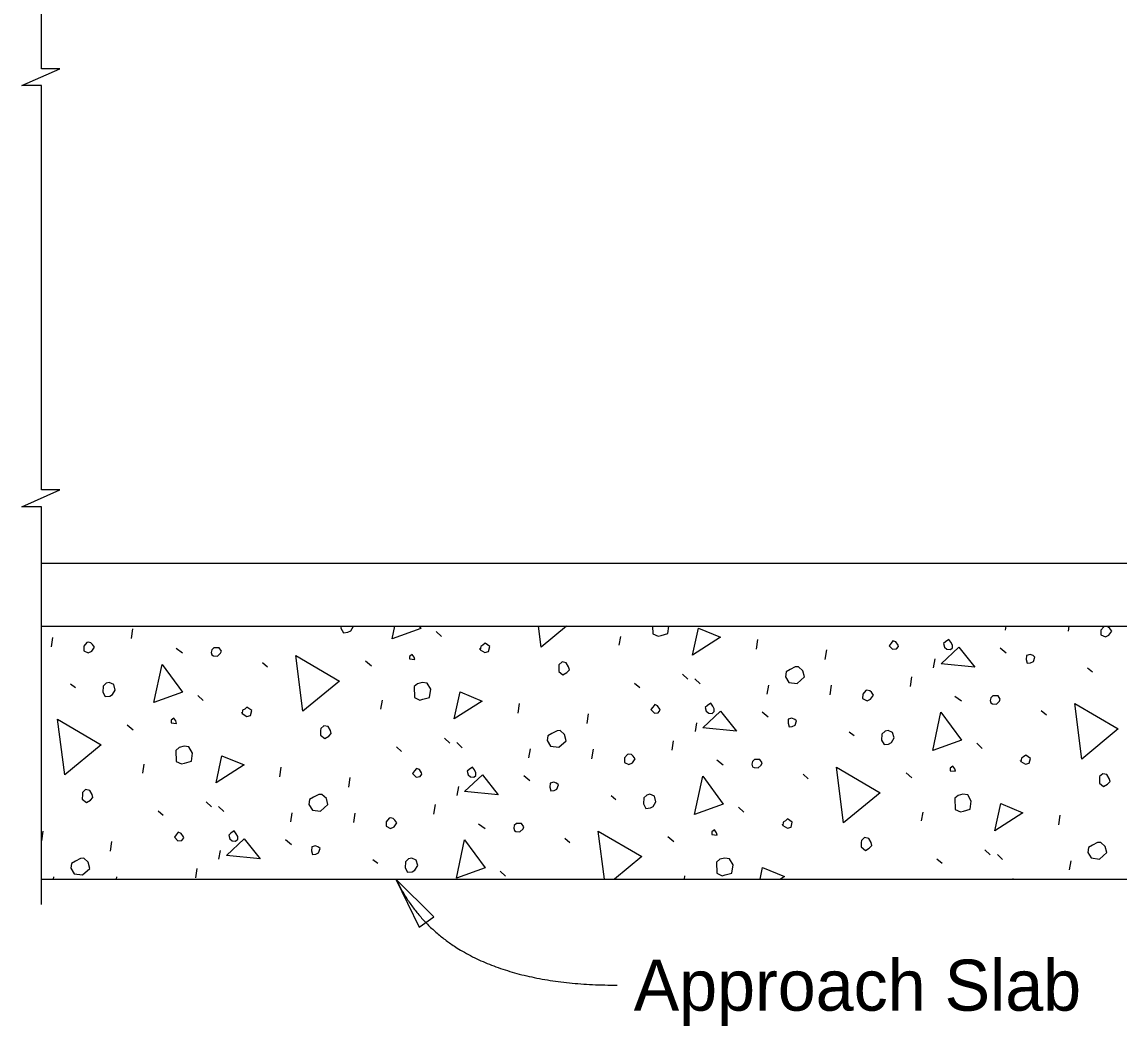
# Model space of a CAD drawing. Extents: x 120680.2 to 120752.3, y 120667.6 to 120707.3.
# Drawn here: x 120705.176 to 120709.513, y 120695.548 to 120699.517 of the extents above; entities that cross this region are included whole.
import ezdxf

# ---------------------------------------------------------------- set-up
doc = ezdxf.new("R2010")
doc.units = 0
for name, color, linetype in [('Dimension', 7, 'Continuous'), ('ParapetConc', 7, 'Continuous'), ('Patterning', 7, 'Continuous'), ('TextStructures', 7, 'Continuous')]:
    doc.layers.add(name, color=color, linetype=linetype)

msp = doc.modelspace()

# ---------------------------------------------------------------- linework, layer by layer
at = {"layer": 'Dimension'}
for points in [[(120705.2532, 120698.3779), (120705.2532, 120699.2651), (120705.1757, 120699.2651), (120705.3257, 120699.3314), (120705.2532, 120699.3314), (120705.2532, 120699.907)], [(120705.2532, 120696.0279), (120705.2532, 120697.6005), (120705.1757, 120697.6005), (120705.3257, 120697.6668), (120705.2532, 120697.6668), (120705.2532, 120698.3779)]]:
    msp.add_lwpolyline(points, dxfattribs=at)
msp.add_lwpolyline([(120706.6543, 120696.1279), (120706.7465, 120695.9379), (120706.8039, 120695.9788)], close=True, dxfattribs=at)
msp.add_open_spline([(120706.6543, 120696.1279), (120706.8547, 120695.7093), (120707.5288, 120695.7093)], degree=2, dxfattribs=at)
at = {"layer": 'ParapetConc'}
for p, q in [((120705.2532, 120697.3779), (120712.7028, 120697.3779)), ((120705.2532, 120697.1279), (120715.7028, 120697.1279)), ((120705.2532, 120696.1279), (120715.7028, 120696.1279))]:
    msp.add_line(p, q, dxfattribs=at)
at = {"layer": 'Patterning'}
for p, q in [((120705.6091, 120697.0796), (120705.6145, 120697.1173)), ((120706.6394, 120697.0787), (120706.6499, 120697.1279)), ((120706.813, 120697.1071), (120706.8339, 120697.0869)), ((120707.2282, 120697.045), (120707.2177, 120697.1279)), ((120707.3288, 120697.1279), (120707.2282, 120697.045)), ((120709.0633, 120697.1122), (120709.066, 120697.1279)), ((120709.3126, 120697.1092), (120709.3153, 120697.1279)), ((120705.2919, 120697.0464), (120705.2973, 120697.0841)), ((120707.5368, 120697.0526), (120707.5428, 120697.0879)), ((120708.0792, 120697.0375), (120708.0846, 120697.0752)), ((120705.785, 120697.0413), (120705.8108, 120697.0223)), ((120708.3515, 120696.9966), (120708.357, 120697.0343)), ((120709.0433, 120697.0422), (120709.0667, 120697.0225)), ((120706.1261, 120696.9852), (120706.1465, 120696.9674)), ((120706.5336, 120696.9908), (120706.5569, 120696.9712)), ((120708.7796, 120696.9637), (120708.7857, 120696.999)), ((120707.7873, 120696.9386), (120707.8083, 120696.9183)), ((120709.3878, 120696.9637), (120709.4075, 120696.9482)), ((120705.3671, 120696.9009), (120705.3868, 120696.8854)), ((120707.5975, 120696.9032), (120707.6178, 120696.8854)), ((120707.8361, 120696.9206), (120707.8571, 120696.9003)), ((120708.1216, 120696.8599), (120708.1276, 120696.8952)), ((120708.3709, 120696.8568), (120708.3763, 120696.8945)), ((120708.6881, 120696.89), (120708.6935, 120696.9277)), ((120705.8712, 120696.8548), (120705.8922, 120696.8345)), ((120708.864, 120696.8518), (120708.8898, 120696.8328)), ((120706.595, 120696.8002), (120706.6011, 120696.8355)), ((120707.1374, 120696.7851), (120707.1428, 120696.8228)), ((120707.4097, 120696.7442), (120707.4152, 120696.7819)), ((120708.1015, 120696.7898), (120708.1249, 120696.7702)), ((120709.2051, 120696.7956), (120709.2254, 120696.7778)), ((120705.5918, 120696.7385), (120705.6152, 120696.7189)), ((120707.8378, 120696.7114), (120707.8439, 120696.7467)), ((120706.8455, 120696.6862), (120706.8665, 120696.6659)), ((120707.7463, 120696.6377), (120707.7517, 120696.6754)), ((120708.4461, 120696.7113), (120708.4657, 120696.6959)), ((120706.6557, 120696.6509), (120706.676, 120696.633)), ((120706.8944, 120696.6682), (120706.9153, 120696.648)), ((120707.1798, 120696.6075), (120707.1859, 120696.6428)), ((120707.4291, 120696.6045), (120707.4345, 120696.6421)), ((120708.9502, 120696.6652), (120708.9711, 120696.645)), ((120707.9222, 120696.5994), (120707.948, 120696.5804)), ((120705.6532, 120696.5479), (120705.6593, 120696.5832)), ((120706.1956, 120696.5328), (120706.201, 120696.5705)), ((120708.2633, 120696.5433), (120708.2836, 120696.5254)), ((120708.6708, 120696.5489), (120708.6941, 120696.5293)), ((120706.468, 120696.4919), (120706.4734, 120696.5296)), ((120707.1597, 120696.5375), (120707.1831, 120696.5178)), ((120706.8961, 120696.459), (120706.9021, 120696.4943)), ((120707.5043, 120696.459), (120707.524, 120696.4435)), ((120705.9038, 120696.4339), (120705.9247, 120696.4136)), ((120705.9526, 120696.4159), (120705.9735, 120696.3956)), ((120706.8045, 120696.3853), (120706.8099, 120696.423)), ((120708.0084, 120696.4129), (120708.0294, 120696.3926)), ((120705.7139, 120696.3985), (120705.7343, 120696.3807)), ((120706.238, 120696.3552), (120706.2441, 120696.3905)), ((120706.4873, 120696.3521), (120706.4927, 120696.3898)), ((120708.7322, 120696.3583), (120708.7383, 120696.3936)), ((120709.2746, 120696.3432), (120709.28, 120696.3809)), ((120706.9804, 120696.3471), (120707.0062, 120696.3281)), ((120705.2538, 120696.2804), (120705.2593, 120696.3181)), ((120706.218, 120696.2851), (120706.2413, 120696.2655)), ((120707.3216, 120696.2909), (120707.3419, 120696.2731)), ((120707.729, 120696.2966), (120707.7524, 120696.277)), ((120705.5262, 120696.2395), (120705.5316, 120696.2772)), ((120705.9543, 120696.2067), (120705.9604, 120696.242)), ((120708.9827, 120696.2443), (120709.0037, 120696.224)), ((120706.5625, 120696.2066), (120706.5822, 120696.1912)), ((120708.7929, 120696.209), (120708.8132, 120696.1911)), ((120709.0315, 120696.2263), (120709.0525, 120696.2061)), ((120709.317, 120696.1656), (120709.3231, 120696.2009)), ((120705.8627, 120696.133), (120705.8682, 120696.1707)), ((120707.0666, 120696.1605), (120707.0876, 120696.1403)), ((120705.3006, 120696.1279), (120705.3023, 120696.1381)), ((120705.5496, 120696.1279), (120705.551, 120696.1375)), ((120707.7942, 120696.1279), (120707.7965, 120696.1413)), ((120708.3381, 120696.1279), (120708.3382, 120696.1285))]:
    msp.add_line(p, q, dxfattribs=at)
for points in [[(120706.4372, 120697.1279), (120706.4368, 120697.1202), (120706.4468, 120697.1022), (120706.4643, 120697.1043), (120706.4758, 120697.1099), (120706.4861, 120697.1279)], [(120706.7465, 120697.1279), (120706.7527, 120697.1195), (120706.6394, 120697.0787)], [(120707.6685, 120697.1279), (120707.6694, 120697.0985), (120707.6902, 120697.0885), (120707.7023, 120697.0918), (120707.7288, 120697.0989), (120707.7327, 120697.1279)], [(120707.8267, 120697.0138), (120707.8497, 120697.1209), (120707.9371, 120697.0848), (120707.8267, 120697.0138)], [(120709.4411, 120697.1125), (120709.4408, 120697.0943), (120709.4586, 120697.0861), (120709.4724, 120697.0924), (120709.4837, 120697.1084), (120709.4756, 120697.1192), (120709.4688, 120697.1251), (120709.4579, 120697.1274), (120709.453, 120697.1261), (120709.4411, 120697.1125)], [(120705.4204, 120697.0497), (120705.4201, 120697.0315), (120705.4378, 120697.0234), (120705.4517, 120697.0296), (120705.4629, 120697.0456), (120705.4548, 120697.0564), (120705.4481, 120697.0623), (120705.4371, 120697.0646), (120705.4323, 120697.0633), (120705.4204, 120697.0497)], [(120708.6035, 120697.0511), (120708.6177, 120697.0368), (120708.6328, 120697.0383), (120708.6405, 120697.0481), (120708.6392, 120697.0529), (120708.6305, 120697.0661), (120708.6189, 120697.0708), (120708.6112, 120697.061), (120708.6035, 120697.0511)], [(120708.8225, 120697.0451), (120708.8323, 120697.0374), (120708.8457, 120697.0358), (120708.8541, 120697.0432), (120708.8539, 120697.0535), (120708.8482, 120697.065), (120708.8402, 120697.0757), (120708.827, 120697.067), (120708.8186, 120697.0596), (120708.8225, 120697.0451)], [(120705.9267, 120697.0146), (120705.9329, 120697.0111), (120705.9486, 120697.0101), (120705.9612, 120697.0212), (120705.9641, 120697.0298), (120705.9554, 120697.043), (120705.9348, 120697.0426), (120705.9264, 120697.0352), (120705.9242, 120697.0243), (120705.9267, 120697.0146)], [(120706.9876, 120697.0349), (120707.006, 120697.0243), (120707.0205, 120697.0281), (120707.0256, 120697.0476), (120707.0066, 120697.0607), (120706.9982, 120697.0532), (120706.9892, 120697.0482), (120706.9876, 120697.0349), (120706.9863, 120697.0397)], [(120708.8091, 120696.9794), (120708.8795, 120697.0449), (120708.9421, 120696.9659), (120708.8091, 120696.9794)], [(120705.6976, 120696.8264), (120705.7297, 120696.9773), (120705.811, 120696.8671), (120705.6976, 120696.8264)], [(120706.2864, 120696.7926), (120706.2585, 120697.0129), (120706.4306, 120696.9115), (120706.2864, 120696.7926)], [(120706.7075, 120696.9986), (120706.7287, 120696.9966), (120706.7261, 120697.0062), (120706.7181, 120697.017), (120706.7073, 120697.0089), (120706.7075, 120696.9986)], [(120707.298, 120696.9679), (120707.2977, 120696.9497), (120707.3143, 120696.9361), (120707.33, 120696.9454), (120707.3401, 120696.9559), (120707.3369, 120696.968), (120707.3275, 120696.9836), (120707.3111, 120696.9869), (120707.2985, 120696.9758), (120707.298, 120696.9679)], [(120709.1459, 120696.9972), (120709.1498, 120696.9827), (120709.1625, 120696.9835), (120709.174, 120696.9892), (120709.1797, 120697.0063), (120709.173, 120697.0122), (120709.1614, 120697.0169), (120709.1469, 120697.013), (120709.1459, 120696.9972)], [(120708.1938, 120696.9284), (120708.2075, 120696.9062), (120708.2397, 120696.9019), (120708.269, 120696.9279), (120708.2625, 120696.952), (120708.2453, 120696.9681), (120708.2326, 120696.9673), (120708.2121, 120696.9566), (120708.1965, 120696.9473), (120708.1938, 120696.9284)], [(120705.4964, 120696.8915), (120705.495, 120696.8679), (120705.505, 120696.8498), (120705.5226, 120696.8519), (120705.534, 120696.8576), (120705.5446, 120696.876), (120705.5388, 120696.8977), (120705.5211, 120696.9059), (120705.509, 120696.9027), (120705.4964, 120696.8915)], [(120706.7263, 120696.8898), (120706.7276, 120696.8461), (120706.7484, 120696.8362), (120706.7605, 120696.8394), (120706.787, 120696.8465), (120706.7914, 120696.8787), (120706.777, 120696.9034), (120706.7582, 120696.9061), (120706.7388, 120696.9009), (120706.7263, 120696.8898)], [(120706.8849, 120696.7615), (120706.908, 120696.8686), (120706.9953, 120696.8325), (120706.8849, 120696.7615)], [(120708.4994, 120696.8602), (120708.4991, 120696.842), (120708.5168, 120696.8338), (120708.5306, 120696.8401), (120708.5419, 120696.856), (120708.5338, 120696.8668), (120708.527, 120696.8728), (120708.5161, 120696.875), (120708.5113, 120696.8737), (120708.4994, 120696.8602)], [(120709.0057, 120696.825), (120709.0118, 120696.8215), (120709.0276, 120696.8206), (120709.0402, 120696.8317), (120709.0431, 120696.8402), (120709.0343, 120696.8534), (120709.0137, 120696.8531), (120709.0054, 120696.8456), (120709.0031, 120696.8347), (120709.0057, 120696.825)], [(120706.0459, 120696.7825), (120706.0642, 120696.7719), (120706.0787, 120696.7758), (120706.0839, 120696.7953), (120706.0648, 120696.8083), (120706.0565, 120696.8009), (120706.0475, 120696.7959), (120706.0459, 120696.7825), (120706.0446, 120696.7874)], [(120707.6617, 120696.7988), (120707.6759, 120696.7845), (120707.691, 120696.7859), (120707.6988, 120696.7958), (120707.6975, 120696.8006), (120707.6887, 120696.8138), (120707.6771, 120696.8185), (120707.6694, 120696.8086), (120707.6617, 120696.7988)], [(120707.8807, 120696.7928), (120707.8906, 120696.7851), (120707.9039, 120696.7835), (120707.9123, 120696.7909), (120707.9121, 120696.8012), (120707.9065, 120696.8126), (120707.8984, 120696.8234), (120707.8852, 120696.8147), (120707.8768, 120696.8073), (120707.8807, 120696.7928)], [(120709.3654, 120696.6031), (120709.3375, 120696.8233), (120709.5096, 120696.7219), (120709.3654, 120696.6031)], [(120705.3447, 120696.5403), (120705.3167, 120696.7606), (120705.4888, 120696.6591), (120705.3447, 120696.5403)], [(120705.7657, 120696.7463), (120705.787, 120696.7442), (120705.7844, 120696.7539), (120705.7763, 120696.7646), (120705.7655, 120696.7566), (120705.7657, 120696.7463)], [(120707.8673, 120696.727), (120707.9377, 120696.7925), (120708.0003, 120696.7135), (120707.8673, 120696.727)], [(120708.2042, 120696.7448), (120708.208, 120696.7304), (120708.2208, 120696.7312), (120708.2322, 120696.7368), (120708.238, 120696.7539), (120708.2312, 120696.7599), (120708.2196, 120696.7645), (120708.2051, 120696.7606), (120708.2042, 120696.7448)], [(120708.7766, 120696.6368), (120708.8086, 120696.7878), (120708.8899, 120696.6775), (120708.7766, 120696.6368)], [(120706.3563, 120696.7156), (120706.356, 120696.6974), (120706.3726, 120696.6837), (120706.3882, 120696.6931), (120706.3983, 120696.7036), (120706.3951, 120696.7156), (120706.3857, 120696.7312), (120706.3693, 120696.7346), (120706.3567, 120696.7235), (120706.3563, 120696.7156)], [(120707.252, 120696.6761), (120707.2657, 120696.6539), (120707.2979, 120696.6496), (120707.3272, 120696.6755), (120707.3207, 120696.6997), (120707.3035, 120696.7157), (120707.2908, 120696.7149), (120707.2703, 120696.7043), (120707.2547, 120696.6949), (120707.252, 120696.6761)], [(120708.5754, 120696.702), (120708.574, 120696.6783), (120708.584, 120696.6603), (120708.6015, 120696.6624), (120708.613, 120696.668), (120708.6236, 120696.6864), (120708.6177, 120696.7081), (120708.6, 120696.7163), (120708.5879, 120696.7131), (120708.5754, 120696.702)], [(120705.7845, 120696.6374), (120705.7859, 120696.5938), (120705.8066, 120696.5838), (120705.8187, 120696.5871), (120705.8453, 120696.5942), (120705.8496, 120696.6264), (120705.8352, 120696.651), (120705.8164, 120696.6537), (120705.7971, 120696.6486), (120705.7845, 120696.6374)], [(120705.9431, 120696.5091), (120705.9662, 120696.6162), (120706.0535, 120696.5801), (120705.9431, 120696.5091)], [(120707.5576, 120696.6078), (120707.5573, 120696.5896), (120707.575, 120696.5814), (120707.5889, 120696.5877), (120707.6001, 120696.6037), (120707.592, 120696.6145), (120707.5853, 120696.6204), (120707.5743, 120696.6227), (120707.5695, 120696.6214), (120707.5576, 120696.6078)], [(120708.0639, 120696.5727), (120708.0701, 120696.5692), (120708.0858, 120696.5682), (120708.0984, 120696.5793), (120708.1013, 120696.5879), (120708.0926, 120696.6011), (120708.072, 120696.6007), (120708.0636, 120696.5933), (120708.0613, 120696.5823), (120708.0639, 120696.5727)], [(120709.1248, 120696.593), (120709.1432, 120696.5824), (120709.1577, 120696.5862), (120709.1628, 120696.6057), (120709.1438, 120696.6187), (120709.1354, 120696.6113), (120709.1264, 120696.6063), (120709.1248, 120696.593), (120709.1235, 120696.5978)], [(120706.7199, 120696.5464), (120706.7341, 120696.5321), (120706.7493, 120696.5336), (120706.757, 120696.5434), (120706.7557, 120696.5483), (120706.747, 120696.5614), (120706.7354, 120696.5661), (120706.7277, 120696.5563), (120706.7199, 120696.5464)], [(120706.939, 120696.5404), (120706.9488, 120696.5327), (120706.9622, 120696.5311), (120706.9705, 120696.5385), (120706.9703, 120696.5488), (120706.9647, 120696.5603), (120706.9566, 120696.571), (120706.9434, 120696.5623), (120706.9351, 120696.5549), (120706.939, 120696.5404)], [(120708.4236, 120696.3507), (120708.3957, 120696.571), (120708.5678, 120696.4696), (120708.4236, 120696.3507)], [(120708.8447, 120696.5567), (120708.8659, 120696.5546), (120708.8633, 120696.5643), (120708.8553, 120696.5751), (120708.8445, 120696.567), (120708.8447, 120696.5567)], [(120709.4352, 120696.526), (120709.4349, 120696.5078), (120709.4515, 120696.4942), (120709.4671, 120696.5035), (120709.4773, 120696.514), (120709.474, 120696.5261), (120709.4647, 120696.5417), (120709.4483, 120696.545), (120709.4357, 120696.5339), (120709.4352, 120696.526)], [(120706.9255, 120696.4747), (120706.996, 120696.5402), (120707.0585, 120696.4612), (120706.9255, 120696.4747)], [(120707.2624, 120696.4925), (120707.2663, 120696.478), (120707.279, 120696.4788), (120707.2904, 120696.4845), (120707.2962, 120696.5016), (120707.2894, 120696.5075), (120707.2778, 120696.5122), (120707.2633, 120696.5083), (120707.2624, 120696.4925)], [(120707.8348, 120696.3845), (120707.8669, 120696.5354), (120707.9482, 120696.4252), (120707.8348, 120696.3845)], [(120705.4145, 120696.4632), (120705.4142, 120696.445), (120705.4308, 120696.4314), (120705.4464, 120696.4407), (120705.4565, 120696.4512), (120705.4533, 120696.4633), (120705.4439, 120696.4789), (120705.4275, 120696.4822), (120705.415, 120696.4711), (120705.4145, 120696.4632)], [(120706.3102, 120696.4237), (120706.324, 120696.4015), (120706.3562, 120696.3972), (120706.3854, 120696.4232), (120706.379, 120696.4473), (120706.3617, 120696.4634), (120706.349, 120696.4626), (120706.3286, 120696.4519), (120706.313, 120696.4426), (120706.3102, 120696.4237)], [(120707.6336, 120696.4496), (120707.6322, 120696.4259), (120707.6422, 120696.4079), (120707.6598, 120696.41), (120707.6712, 120696.4157), (120707.6818, 120696.4341), (120707.676, 120696.4558), (120707.6582, 120696.464), (120707.6462, 120696.4607), (120707.6336, 120696.4496)], [(120708.8635, 120696.4479), (120708.8648, 120696.4042), (120708.8856, 120696.3943), (120708.8977, 120696.3975), (120708.9242, 120696.4046), (120708.9286, 120696.4368), (120708.9142, 120696.4615), (120708.8953, 120696.4642), (120708.876, 120696.459), (120708.8635, 120696.4479)], [(120709.0221, 120696.3196), (120709.0452, 120696.4267), (120709.1325, 120696.3905), (120709.0221, 120696.3196)], [(120706.6158, 120696.3555), (120706.6155, 120696.3373), (120706.6332, 120696.3291), (120706.6471, 120696.3354), (120706.6583, 120696.3513), (120706.6503, 120696.3621), (120706.6435, 120696.3681), (120706.6325, 120696.3703), (120706.6277, 120696.369), (120706.6158, 120696.3555)], [(120707.1222, 120696.3203), (120707.1283, 120696.3168), (120707.1441, 120696.3159), (120707.1566, 120696.327), (120707.1595, 120696.3355), (120707.1508, 120696.3487), (120707.1302, 120696.3484), (120707.1218, 120696.341), (120707.1196, 120696.33), (120707.1222, 120696.3203)], [(120708.1831, 120696.3406), (120708.2014, 120696.33), (120708.2159, 120696.3339), (120708.221, 120696.3534), (120708.202, 120696.3664), (120708.1937, 120696.359), (120708.1847, 120696.354), (120708.1831, 120696.3406), (120708.1818, 120696.3454)], [(120705.7782, 120696.2941), (120705.7923, 120696.2798), (120705.8075, 120696.2812), (120705.8152, 120696.2911), (120705.8139, 120696.2959), (120705.8052, 120696.3091), (120705.7936, 120696.3138), (120705.7859, 120696.3039), (120705.7782, 120696.2941)], [(120705.9837, 120696.2224), (120706.0542, 120696.2878), (120706.1168, 120696.2088), (120705.9837, 120696.2224)], [(120705.9972, 120696.2881), (120706.007, 120696.2804), (120706.0204, 120696.2788), (120706.0287, 120696.2862), (120706.0286, 120696.2965), (120706.0229, 120696.3079), (120706.0149, 120696.3187), (120706.0017, 120696.31), (120705.9933, 120696.3026), (120705.9972, 120696.2881)], [(120706.8931, 120696.1321), (120706.9251, 120696.2831), (120707.0064, 120696.1728), (120706.8931, 120696.1321)], [(120707.4781, 120696.1279), (120707.4539, 120696.3186), (120707.626, 120696.2172), (120707.5177, 120696.1279)], [(120707.9029, 120696.3044), (120707.9242, 120696.3023), (120707.9216, 120696.312), (120707.9135, 120696.3227), (120707.9027, 120696.3147), (120707.9029, 120696.3044)], [(120708.4935, 120696.2737), (120708.4932, 120696.2555), (120708.5098, 120696.2418), (120708.5254, 120696.2512), (120708.5355, 120696.2616), (120708.5323, 120696.2737), (120708.5229, 120696.2893), (120708.5065, 120696.2927), (120708.4939, 120696.2816), (120708.4935, 120696.2737)], [(120706.3206, 120696.2401), (120706.3245, 120696.2257), (120706.3372, 120696.2265), (120706.3486, 120696.2321), (120706.3544, 120696.2492), (120706.3476, 120696.2552), (120706.336, 120696.2598), (120706.3215, 120696.2559), (120706.3206, 120696.2401)], [(120709.3892, 120696.2342), (120709.4029, 120696.212), (120709.4351, 120696.2076), (120709.4644, 120696.2336), (120709.4579, 120696.2578), (120709.4407, 120696.2738), (120709.428, 120696.273), (120709.4075, 120696.2624), (120709.3919, 120696.253), (120709.3892, 120696.2342)], [(120705.3685, 120696.1714), (120705.3822, 120696.1492), (120705.4144, 120696.1449), (120705.4437, 120696.1708), (120705.4372, 120696.195), (120705.4199, 120696.211), (120705.4072, 120696.2102), (120705.3868, 120696.1996), (120705.3712, 120696.1902), (120705.3685, 120696.1714)], [(120706.6918, 120696.1973), (120706.6904, 120696.1736), (120706.7004, 120696.1556), (120706.718, 120696.1577), (120706.7294, 120696.1633), (120706.74, 120696.1817), (120706.7342, 120696.2034), (120706.7165, 120696.2116), (120706.7044, 120696.2084), (120706.6918, 120696.1973)], [(120707.9217, 120696.1955), (120707.923, 120696.1519), (120707.9438, 120696.1419), (120707.9559, 120696.1452), (120707.9825, 120696.1523), (120707.9868, 120696.1845), (120707.9724, 120696.2091), (120707.9536, 120696.2118), (120707.9343, 120696.2067), (120707.9217, 120696.1955)], [(120708.0934, 120696.1279), (120708.1034, 120696.1743), (120708.1907, 120696.1382), (120708.1747, 120696.1279)], [(120709.0947, 120696.1279), (120709.0938, 120696.1291), (120709.092, 120696.1279)]]:
    msp.add_lwpolyline(points, dxfattribs=at)

# ---------------------------------------------------------------- texts
at = {"layer": 'TextStructures'}
msp.add_text('Approach Slab', height=0.2016, dxfattribs=at).set_placement((120707.5941, 120695.6084))

doc.saveas('drawing.dxf')
